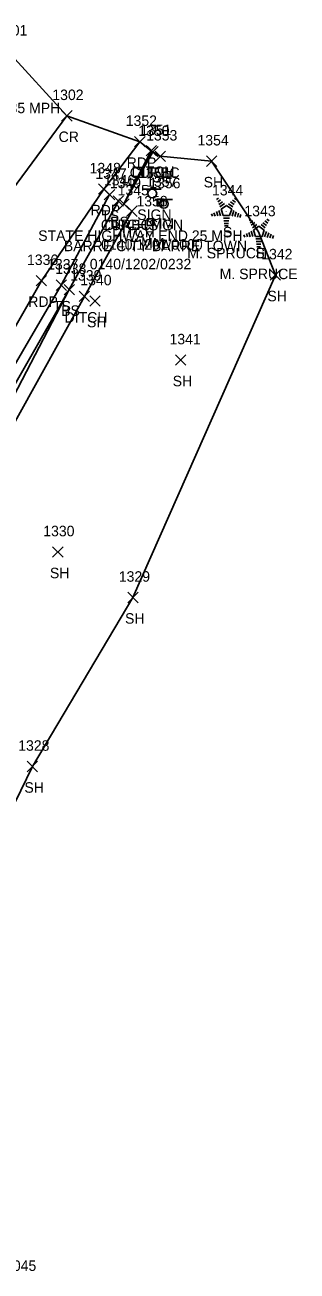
# Model space of a CAD drawing. Extents: x 1639430 to 1640195, y 612006 to 612917.
# Drawn here: x 1639980.2 to 1640032, y 612647.8 to 612885.5 of the extents above; entities that cross this region are included whole.
import ezdxf

# ---------------------------------------------------------------- set-up
doc = ezdxf.new("R2010")
doc.units = 0
for name, color, linetype in [('D_A', 7, 'Continuous'), ('D_I', 7, 'Continuous'), ('D_TIC', 7, 'Continuous'), ('DD', 7, 'Continuous'), ('L_A', 7, 'Continuous'), ('L_C', 7, 'Continuous'), ('L_I', 7, 'Continuous'), ('L_TIC', 7, 'Continuous'), ('LELB', 7, 'Continuous'), ('LSOGP', 7, 'Continuous'), ('LTC', 7, 'Continuous'), ('P_A', 7, 'Continuous'), ('P_I', 7, 'Continuous'), ('P_TIC', 7, 'Continuous'), ('PET', 7, 'Continuous'), ('PRC', 7, 'Continuous'), ('R_A', 7, 'Continuous'), ('R_I', 7, 'Continuous'), ('R_TIC', 7, 'Continuous'), ('RC', 7, 'Continuous'), ('S_A', 7, 'Continuous'), ('S_C', 7, 'Continuous'), ('S_I', 7, 'Continuous'), ('SRM', 7, 'Continuous'), ('SSGN', 7, 'Continuous')]:
    doc.layers.add(name, color=color, linetype=linetype)

msp = doc.modelspace()

# ---------------------------------------------------------------- linework, layer by layer
at = {"layer": 'D_TIC'}
for points in [[(1640003.27, 612860.49), (1640005.27, 612862.49)], [(1640005.27, 612860.49), (1640003.27, 612862.49)], [(1639998.06, 612850.35), (1640000.06, 612852.35)], [(1640000.06, 612850.35), (1639998.06, 612852.35)], [(1639999.55, 612848.98), (1640001.55, 612850.98)], [(1640001.55, 612848.98), (1639999.55, 612850.98)], [(1639990.51, 612832.72), (1639992.51, 612834.72)], [(1639992.51, 612832.72), (1639990.51, 612834.72)]]:
    msp.add_lwpolyline(points, dxfattribs=at)
at = {"layer": 'DD'}
msp.add_lwpolyline([(1639927.28, 612709.49), (1639934.25, 612725.09), (1639952.02, 612760.27), (1639969.9, 612794.69), (1639991.51, 612833.72), (1640000.55, 612849.98), (1639999.06, 612851.35), (1640004.27, 612861.49)], dxfattribs=at)
at = {"layer": 'L_TIC'}
for points in [[(1640004.98, 612859.44), (1640006.98, 612861.44)], [(1640006.98, 612859.44), (1640004.98, 612861.44)], [(1640014.76, 612858.5), (1640016.76, 612860.5)], [(1640016.76, 612858.5), (1640014.76, 612860.5)], [(1639995.31, 612852.13), (1639997.31, 612854.13)], [(1639997.31, 612852.13), (1639995.31, 612854.13)], [(1639996.99, 612850.89), (1639998.99, 612852.89)], [(1639998.99, 612850.89), (1639996.99, 612852.89)], [(1640026.92, 612836.78), (1640028.92, 612838.78)], [(1640028.92, 612836.78), (1640026.92, 612838.78)], [(1639986.12, 612834.84), (1639988.12, 612836.84)], [(1639988.12, 612834.84), (1639986.12, 612836.84)], [(1639987.64, 612834), (1639989.64, 612836)], [(1639989.64, 612834), (1639987.64, 612836)], [(1639987.64, 612834), (1639989.64, 612836)], [(1639989.64, 612834), (1639987.64, 612836)], [(1639992.53, 612831.83), (1639994.53, 612833.83)], [(1639994.53, 612831.83), (1639992.53, 612833.83)], [(1640008.86, 612820.57), (1640010.86, 612822.57)], [(1640010.86, 612820.57), (1640008.86, 612822.57)], [(1639985.46, 612783.96), (1639987.46, 612785.96)], [(1639987.46, 612783.96), (1639985.46, 612785.96)], [(1639999.78, 612775.29), (1640001.78, 612777.29)], [(1640001.78, 612775.29), (1639999.78, 612777.29)], [(1639980.6, 612743.05), (1639982.6, 612745.05)], [(1639982.6, 612743.05), (1639980.6, 612745.05)]]:
    msp.add_lwpolyline(points, dxfattribs=at)
at = {"layer": 'LELB'}
for points in [[(1639920.56, 612713.35), (1639928.08, 612729.31), (1639945.96, 612762.85), (1639965.37, 612798.68), (1639987.12, 612835.84), (1639996.31, 612853.13)], [(1639923.98, 612711.48), (1639930.58, 612727.96), (1639948.36, 612761.64), (1639966.87, 612797.15), (1639988.64, 612835), (1639997.99, 612851.89)], [(1639925.69, 612710.85), (1639932.54, 612726.53), (1639949.92, 612761.12), (1639968.23, 612795.93), (1639988.64, 612835)]]:
    msp.add_lwpolyline(points, dxfattribs=at)
at = {"layer": 'LSOGP'}
msp.add_lwpolyline([(1639965.85, 612711.74), (1639981.6, 612744.05), (1640000.78, 612776.29), (1640027.92, 612837.78), (1640024.7, 612846), (1640015.76, 612859.5), (1640005.98, 612860.43), (1640004.57, 612861.31), (1640004.27, 612861.49), (1640002.09, 612863.22), (1639988.18, 612868.16), (1639976.9, 612880.46)], dxfattribs=at)
at = {"layer": 'LTC'}
for p, q in [((1640016.72, 612852.18), (1640017.08, 612852.44)), ((1640020.12, 612852.42), (1640020.54, 612852.12)), ((1640016.93, 612851.72), (1640017.46, 612852.1)), ((1640017.12, 612850.11), (1640017.45, 612849.09)), ((1640017.14, 612851.25), (1640017.85, 612851.76)), ((1640017.35, 612850.78), (1640018.23, 612851.42)), ((1640017.58, 612850.33), (1640018.59, 612851.06)), ((1640017.58, 612850.33), (1640017.96, 612849.14)), ((1640018.59, 612851.06), (1640019.59, 612850.34)), ((1640019.01, 612851.38), (1640019.82, 612850.79)), ((1640019.59, 612850.34), (1640019.19, 612849.14)), ((1640019.38, 612851.72), (1640020.06, 612851.23)), ((1640020.02, 612850.07), (1640019.68, 612849.03)), ((1640019.75, 612852.07), (1640020.3, 612851.67)), ((1640015.76, 612849.46), (1640015.91, 612848.99)), ((1640016.21, 612849.68), (1640016.42, 612849.03)), ((1640016.67, 612849.89), (1640016.94, 612849.06)), ((1640019.19, 612849.14), (1640017.96, 612849.14)), ((1640019.16, 612848.64), (1640018.01, 612848.64)), ((1640019.07, 612848.14), (1640018.08, 612848.14)), ((1640018.99, 612847.64), (1640018.16, 612847.64)), ((1640020.47, 612849.82), (1640020.18, 612848.93)), ((1640020.91, 612849.57), (1640020.67, 612848.84)), ((1640021.36, 612849.32), (1640021.17, 612848.74)), ((1640022.9, 612848.2), (1640023.25, 612848.46)), ((1640023.11, 612847.74), (1640023.64, 612848.12)), ((1640023.32, 612847.27), (1640024.02, 612847.78)), ((1640025.55, 612847.75), (1640026.23, 612847.25)), ((1640025.92, 612848.1), (1640026.47, 612847.7)), ((1640026.3, 612848.45), (1640026.71, 612848.14)), ((1640018.9, 612847.14), (1640018.23, 612847.14)), ((1640021.93, 612845.48), (1640022.08, 612845.02)), ((1640022.38, 612845.7), (1640022.6, 612845.05)), ((1640022.84, 612845.92), (1640023.11, 612845.08)), ((1640023.3, 612846.13), (1640023.63, 612845.11)), ((1640023.53, 612846.81), (1640024.4, 612847.45)), ((1640023.75, 612846.35), (1640024.76, 612847.09)), ((1640023.75, 612846.35), (1640024.14, 612845.16)), ((1640025.37, 612845.16), (1640024.14, 612845.16)), ((1640024.76, 612847.09), (1640025.76, 612846.36)), ((1640025.18, 612847.4), (1640025.99, 612846.81)), ((1640025.76, 612846.36), (1640025.37, 612845.16)), ((1640026.2, 612846.09), (1640025.86, 612845.05)), ((1640026.64, 612845.84), (1640026.35, 612844.96)), ((1640027.09, 612845.59), (1640026.85, 612844.86)), ((1640027.53, 612845.34), (1640027.34, 612844.77)), ((1640025.33, 612844.66), (1640024.18, 612844.66)), ((1640025.25, 612844.16), (1640024.26, 612844.16)), ((1640025.16, 612843.66), (1640024.33, 612843.66)), ((1640025.08, 612843.16), (1640024.4, 612843.16))]:
    msp.add_line(p, q, dxfattribs=at)
at = {"layer": 'P_TIC'}
for points in [[(1639987.18, 612867.16), (1639989.18, 612869.16)], [(1639989.18, 612867.16), (1639987.18, 612869.16)], [(1640001.09, 612862.22), (1640003.09, 612864.22)], [(1640003.09, 612862.22), (1640001.09, 612864.22)], [(1639994.21, 612853.18), (1639996.21, 612855.18)], [(1639996.21, 612853.18), (1639994.21, 612855.18)], [(1639982.33, 612835.7), (1639984.33, 612837.7)], [(1639984.33, 612835.7), (1639982.33, 612837.7)]]:
    msp.add_lwpolyline(points, dxfattribs=at)
at = {"layer": 'PET'}
msp.add_lwpolyline([(1639918, 612716.74), (1639925.91, 612731.74), (1639943.29, 612763.86), (1639962.3, 612799.99), (1639983.33, 612836.7), (1639995.21, 612854.18), (1640002.09, 612863.22)], dxfattribs=at)
at = {"layer": 'PRC'}
msp.add_lwpolyline([(1639988.18, 612868.16), (1639972.03, 612846.35), (1639947.21, 612799.98), (1639926.52, 612762.8), (1639908.46, 612730.93)], dxfattribs=at)
at = {"layer": 'R_TIC'}
for points in [[(1640003.57, 612860.31), (1640005.57, 612862.31)], [(1640005.57, 612860.31), (1640003.57, 612862.31)], [(1639998.06, 612850.35), (1640000.06, 612852.35)], [(1640000.06, 612850.35), (1639998.06, 612852.35)]]:
    msp.add_lwpolyline(points, dxfattribs=at)
at = {"layer": 'RC'}
msp.add_lwpolyline([(1639999.06, 612851.35), (1640004.57, 612861.31)], dxfattribs=at)
at = {"layer": 'SRM'}
for points in [[(1640005.36, 612852.25), (1640006.61, 612852.25), (1640006.61, 612851), (1640005.36, 612851)], [(1640003.5, 612848.5), (1640004.75, 612848.5), (1640004.75, 612847.25), (1640003.5, 612847.25)]]:
    msp.add_lwpolyline(points, close=True, dxfattribs=at)
for centre in [(1640005.99, 612851.62), (1640004.13, 612847.88)]:
    msp.add_circle(centre, 0.0833, dxfattribs=at)
at = {"layer": 'SSGN'}
for p, q in [((1640002.81, 612854.15), (1640006.15, 612854.15)), ((1640004.46, 612853.32), (1640004.46, 612853.32)), ((1640005, 612852.18), (1640008.34, 612852.18)), ((1640006.65, 612851.35), (1640006.65, 612851.35))]:
    msp.add_line(p, q, dxfattribs=at)
for centre in [(1640004.46, 612853.32), (1640006.65, 612851.35)]:
    msp.add_circle(centre, 0.833, dxfattribs=at)

# ---------------------------------------------------------------- texts
at = {"layer": 'D_A'}
for p in [(1640000.51, 612856.49), (1639995.3, 612846.35), (1639996.79, 612844.98), (1639987.75, 612828.72)]:
    msp.add_text('DITCH', height=2, dxfattribs=at).set_placement(p)
at = {"layer": 'D_I'}
for s, p in [('1351', (1640002.15, 612864.49)), ('1349', (1639996.36, 612854.35)), ('1345', (1639997.86, 612852.98)), ('1339', (1639988.81, 612836.72))]:
    msp.add_text(s, height=2, dxfattribs=at).set_placement(p)
at = {"layer": 'L_A'}
for s, p in [('SH', (1640004.47, 612855.44)), ('SH', (1640014.25, 612854.5)), ('TS', (1639994.72, 612848.13)), ('BS', (1639996.43, 612846.89)), ('S', (1640017.91, 612844.97)), ('S', (1640024.09, 612841)), ('SH', (1640026.4, 612832.78)), ('TS', (1639985.53, 612830.84)), ('BS', (1639987.08, 612830)), ('BS', (1639987.08, 612830)), ('SH', (1639992.02, 612827.83)), ('SH', (1640008.35, 612816.57)), ('SH', (1639984.95, 612779.96)), ('SH', (1639999.27, 612771.29)), ('SH', (1639980.09, 612739.05))]:
    msp.add_text(s, height=2, dxfattribs=at).set_placement(p)
at = {"layer": 'L_C'}
for p in [(1640011.13, 612840.97), (1640017.3, 612837)]:
    msp.add_text('M. SPRUCE', height=2, dxfattribs=at).set_placement(p)
at = {"layer": 'L_I'}
for s, p in [('1353', (1640003.28, 612863.44)), ('1354', (1640013.07, 612862.5)), ('1347', (1639993.62, 612856.13)), ('1346', (1639995.24, 612854.89)), ('1344', (1640015.84, 612852.97)), ('1343', (1640022.01, 612849)), ('1342', (1640025.22, 612840.78)), ('1337', (1639984.42, 612838.84)), ('1338', (1639985.95, 612838)), ('1338', (1639985.95, 612838)), ('1340', (1639990.75, 612835.83)), ('1341', (1640007.74, 612824.57)), ('1330', (1639983.68, 612787.96)), ('1329', (1639998.08, 612779.29)), ('1328', (1639978.91, 612747.05))]:
    msp.add_text(s, height=2, dxfattribs=at).set_placement(p)
at = {"layer": 'LTC'}
for p in [(1640018.47, 612850.08), (1640024.64, 612846.1)]:
    msp.add_text('.', height=1.04, rotation=270, dxfattribs=at).set_placement(p)
at = {"layer": 'P_A'}
for s, p in [('CR', (1639986.61, 612863.16)), ('RDP', (1639999.58, 612858.22)), ('RDP', (1639992.7, 612849.18)), ('RDP', (1639980.82, 612831.7))]:
    msp.add_text(s, height=2, dxfattribs=at).set_placement(p)
at = {"layer": 'P_I'}
for s, p in [('1301', (1639974.7, 612883.46)), ('1302', (1639985.41, 612871.16)), ('1352', (1639999.4, 612866.22)), ('1348', (1639992.51, 612857.18)), ('1336', (1639980.58, 612839.7))]:
    msp.add_text(s, height=2, dxfattribs=at).set_placement(p)
at = {"layer": 'R_A'}
for p in [(1640000.16, 612856.31), (1639994.65, 612846.35)]:
    msp.add_text('CURBC', height=2, dxfattribs=at).set_placement(p)
at = {"layer": 'R_I'}
for s, p in [('1350', (1640001.79, 612864.31)), ('1349', (1639996.36, 612854.35)), ('1045', (1639976.4, 612647.84))]:
    msp.add_text(s, height=2, dxfattribs=at).set_placement(p)
at = {"layer": 'S_A'}
for s, p in [('SIGN', (1640001.6, 612848.3)), ('SIGN', (1640003.79, 612846.33)), ('MM', (1640004.17, 612846.62)), ('MM', (1640002.32, 612842.88))]:
    msp.add_text(s, height=2, dxfattribs=at).set_placement(p)
at = {"layer": 'S_C'}
for s, p in [('STATE HIGHWAY BEGIN 35 MPH', (1639945.31, 612868.65)), ('STATE HIGHWAY END 25 MPH', (1639982.72, 612844.3)), ('BARRE CITY BARRE TOWN', (1639987.6, 612842.33)), ('0140/1201/0000', (1639994.73, 612842.62)), ('0140/1202/0232', (1639992.55, 612838.88))]:
    msp.add_text(s, height=2, dxfattribs=at).set_placement(p)
at = {"layer": 'S_I'}
for s, p in [('1355', (1640001.75, 612856.3)), ('1357', (1640003.29, 612854.62)), ('1356', (1640003.88, 612854.33)), ('1358', (1640001.44, 612850.88))]:
    msp.add_text(s, height=2, dxfattribs=at).set_placement(p)

doc.saveas('drawing.dxf')
